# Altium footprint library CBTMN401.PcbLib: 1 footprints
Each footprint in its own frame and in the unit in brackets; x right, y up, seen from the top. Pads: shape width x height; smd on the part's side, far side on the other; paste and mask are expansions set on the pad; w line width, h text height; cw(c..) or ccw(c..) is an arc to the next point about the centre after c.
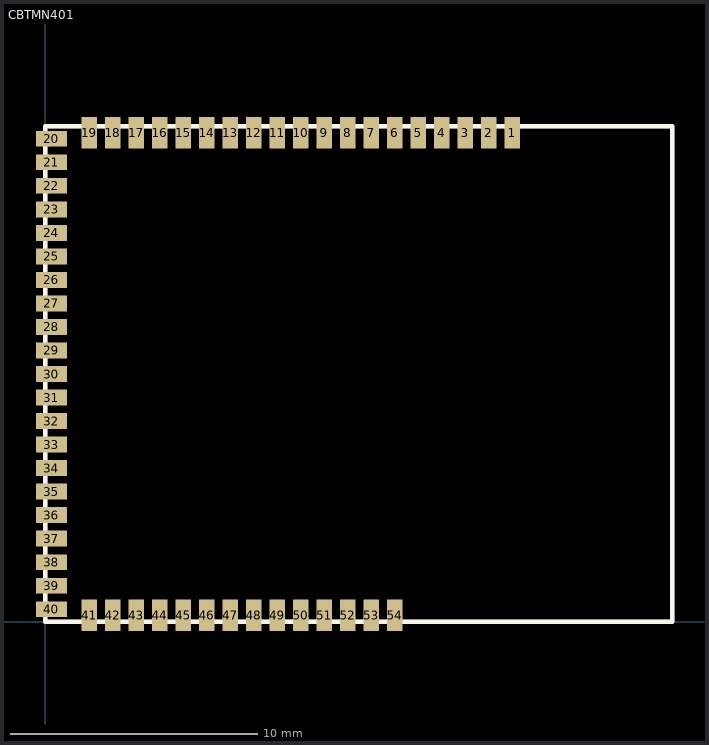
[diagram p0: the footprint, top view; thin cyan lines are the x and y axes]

## CBTMN401 [mil]
pads (54):
  rect 25x50 smd mask+2.5: 1(745,780) 2(707.5,780) 3(670,780) 4(632.5,780) 5(595,780) 6(557.5,780) 7(520,780) 8(482.5,780) 9(445,780) 10(407.5,780) 11(370,780) 12(332.5,780) 13(295,780) 14(257.5,780) 15(220,780) 16(182.5,780) 17(145,780) 18(107.5,780) 19(70,780) 41(70,10) 42(107.5,10) 43(145,10) 44(182.5,10) 45(220,10) 46(257.5,10) 47(295,10) 48(332.5,10) 49(370,10) 50(407.5,10) 51(445,10) 52(482.5,10) 53(520,10) 54(557.5,10)
  rect 50x25 smd mask+2.5: 20(10,770) 21(10,732.5) 22(10,695) 23(10,657.5) 24(10,620) 25(10,582.5) 26(10,545) 27(10,507.5) 28(10,470) 29(10,432.5) 30(10,395) 31(10,357.5) 32(10,320) 33(10,282.5) 34(10,245) 35(10,207.5) 36(10,170) 37(10,132.5) 38(10,95) 39(10,57.5) 40(10,20)
L26-Silk Screen Top (Multiple PADS layers...):
  lines w7: 0,0 1000,0 1000,790 0,790 0,0
L15 (Multiple PADS layers...):
  lines w7: 0,10 ccw(c0,20) 0,30 ; 0,47.5 ccw(c0,57.5) 0,67.5 ; 0,85 ccw(c0,95) 0,105 ; 0,122.5 ccw(c0,132.5) 0,142.5 ; 0,160 ccw(c0,170) 0,180 ; 0,197.5 ccw(c0,207.5) 0,217.5 ; 0,235 ccw(c0,245) 0,255 ; 0,272.5 ccw(c0,282.5) 0,292.5 ; 0,310 ccw(c0,320) 0,330 ; 0,347.5 ccw(c0,357.5) 0,367.5 ; 0,385 ccw(c0,395) 0,405 ; 0,422.5 ccw(c0,432.5) 0,442.5 ; 0,460 ccw(c0,470) 0,480 ; 0,497.5 ccw(c0,507.5) 0,517.5 ; 0,535 ccw(c0,545) 0,555 ; 0,572.5 ccw(c0,582.5) 0,592.5 ; 0,610 ccw(c0,620) 0,630 ; 0,647.5 ccw(c0,657.5) 0,667.5 ; 0,685 ccw(c0,695) 0,705 ; 0,722.5 ccw(c0,732.5) 0,742.5 ; 0,760 ccw(c0,770) 0,780 ; 60,0 cw(c70,0) 80,0 ; 60,790 ccw(c70,790) 80,790 ; 97.5,0 cw(c107.5,0) 117.5,0 ; 97.5,790 ccw(c107.5,790) 117.5,790 ; 135,0 cw(c145,0) 155,0 ; 135,790 ccw(c145,790) 155,790 ; 172.5,0 cw(c182.5,0) 192.5,0 ; 172.5,790 ccw(c182.5,790) 192.5,790 ; 210,0 cw(c220,0) 230,0 ; 210,790 ccw(c220,790) 230,790 ; 247.5,0 cw(c257.5,0) 267.5,0 ; 247.5,790 ccw(c257.5,790) 267.5,790 ; 285,0 cw(c295,0) 305,0 ; 285,790 ccw(c295,790) 305,790 ; 322.5,0 cw(c332.5,0) 342.5,0 ; 322.5,790 ccw(c332.5,790) 342.5,790 ; 360,0 cw(c370,0) 380,0 ; 360,790 ccw(c370,790) 380,790 ; 397.5,0 cw(c407.5,0) 417.5,0 ; 397.5,790 ccw(c407.5,790) 417.5,790 ; 435,0 cw(c445,0) 455,0 ; 435,790 ccw(c445,790) 455,790 ; 472.5,0 cw(c482.5,0) 492.5,0 ; 472.5,790 ccw(c482.5,790) 492.5,790 ; 510,0 cw(c520,0) 530,0 ; 510,790 ccw(c520,790) 530,790 ; 547.5,0 cw(c557.5,0) 567.5,0 ; 547.5,790 ccw(c557.5,790) 567.5,790 ; 585,790 ccw(c595,790) 605,790 ; 622.5,790 ccw(c632.5,790) 642.5,790 ; 660,790 ccw(c670,790) 680,790 ; 697.5,790 ccw(c707.5,790) 717.5,790 ; 735,790 ccw(c745,790) 755,790 ; 0,0 1000,0 1000,790 0,790 0,0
